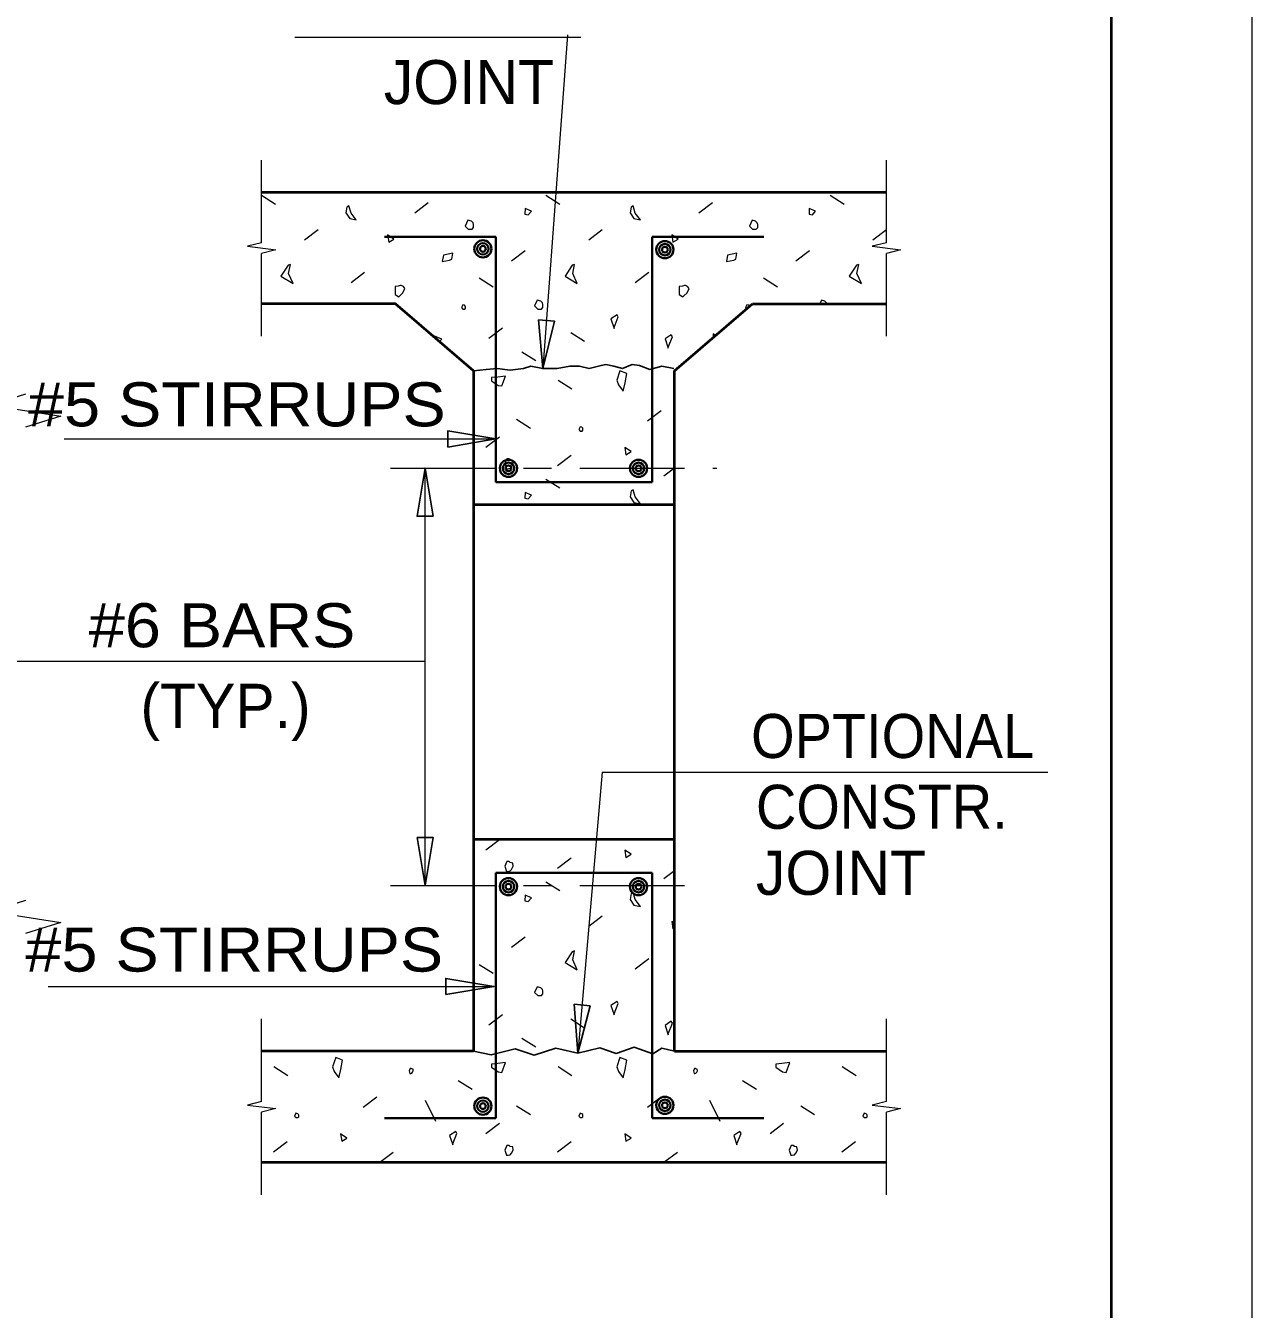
# Model space of a CAD drawing. Extents: x 0 to 34, y 0 to 23.4.
# Drawn here: x 29.648 to 34, y 4.606 to 9.162 of the extents above; entities that cross this region are included whole.
import ezdxf
from ezdxf.enums import TextEntityAlignment as Align

# ---------------------------------------------------------------- set-up
doc = ezdxf.new("R2010")
doc.units = 0
doc.header["$LTSCALE"] = 0.062
doc.linetypes.add('LONG_DASH_SHORT_DASH', pattern=[9.9, 6, -1.2, 1.5, -1.2])
doc.linetypes.add('SHORT_DASHED', pattern=[2.7, 1.5, -1.2])
for name, color, linetype, lineweight in [('1', 7, 'Continuous', 40), ('2', 7, 'SHORT_DASHED', 13), ('3', 7, 'Continuous', 35), ('4', 7, 'Continuous', 13), ('7', 7, 'Continuous', 13)]:
    doc.layers.add(name, color=color, linetype=linetype, lineweight=lineweight)

msp = doc.modelspace()

# ---------------------------------------------------------------- linework, layer by layer
at = {"layer": '1', "lineweight": 13}
for p, q in [((30.485, 8.39125), (30.485, 8.685)), ((32.70167, 8.39125), (32.70167, 8.685)), ((30.485, 8.06), (30.485, 8.35375)), ((32.70167, 8.06), (32.70167, 8.35375)), ((30.485, 5.34333), (30.485, 5.63708)), ((32.70167, 5.34333), (32.70167, 5.63708)), ((30.485, 5.01208), (30.485, 5.30583)), ((32.70167, 5.01208), (32.70167, 5.30583))]:
    msp.add_line(p, q, dxfattribs=at)
at = {"layer": '1'}
for p, q in [((30.485, 8.57042), (32.70167, 8.57042)), ((31.94958, 7.93708), (32.22667, 8.17458)), ((32.22667, 8.17458), (32.70167, 8.17458)), ((31.23708, 7.93708), (31.23708, 5.5225)), ((31.94958, 5.5225), (31.94958, 7.93708)), ((31.23708, 7.46208), (31.94958, 7.46208)), ((31.23708, 6.27458), (31.94958, 6.27458)), ((31.23708, 5.5225), (30.485, 5.5225)), ((31.94958, 5.5225), (32.70167, 5.5225)), ((32.70167, 5.12667), (30.485, 5.12667))]:
    msp.add_line(p, q, dxfattribs=at)
at = {"layer": '1', "lineweight": 13}
for points in [[(34, 0), (34, 22), (0, 22)], [(30.485, 8.39125), (30.435, 8.37875), (30.535, 8.36625), (30.485, 8.35375)], [(32.70167, 8.39125), (32.65167, 8.37875), (32.75167, 8.36625), (32.70167, 8.35375)], [(29.6476, 7.85406), (29.5226, 7.815), (29.7726, 7.77594), (29.6476, 7.73688)], [(29.6476, 6.05719), (29.5226, 6.01813), (29.7726, 5.97906), (29.6476, 5.94)], [(30.485, 5.34333), (30.435, 5.33083), (30.535, 5.31833), (30.485, 5.30583)], [(32.70167, 5.34333), (32.65167, 5.33083), (32.75167, 5.31833), (32.70167, 5.30583)]]:
    msp.add_lwpolyline(points, dxfattribs=at)
at = {"layer": '1'}
msp.add_lwpolyline([(33.5, 0.5), (33.5, 21.5), (1.5, 21.5), (1.5, 0.5)], close=True, dxfattribs=at)
msp.add_lwpolyline([(31.23708, 7.93708), (30.96, 8.17458), (30.485, 8.17458)], dxfattribs=at)
at = {"layer": '1', "lineweight": 25}
for points in [[(31.23708, 7.93708), (31.2813, 7.94203), (31.32099, 7.94484), (31.36625, 7.93922), (31.41443, 7.94484), (31.43995, 7.95333), (31.48245, 7.94484), (31.53339, 7.94484), (31.5787, 7.95333), (31.61271, 7.95333), (31.64672, 7.94484), (31.68917, 7.9562), (31.7062, 7.95906), (31.73448, 7.95333), (31.76568, 7.94484), (31.79964, 7.95906), (31.8251, 7.9562), (31.86193, 7.94203), (31.90443, 7.95333), (31.94693, 7.94484)], [(31.23708, 5.5225), (31.2999, 5.50932), (31.38474, 5.5312), (31.45156, 5.50802), (31.5287, 5.5325), (31.60708, 5.51578), (31.68547, 5.53375), (31.74333, 5.51448), (31.8063, 5.53635), (31.87313, 5.51318), (31.90526, 5.5325), (31.94958, 5.5225)]]:
    msp.add_lwpolyline(points, dxfattribs=at)
at = {"layer": '2', "linetype": 'LONG_DASH_SHORT_DASH'}
for p, q in [((30.94188, 7.59188), (32.10052, 7.59188)), ((30.94188, 6.11021), (32.01578, 6.11021))]:
    msp.add_line(p, q, dxfattribs=at)
at = {"layer": '3'}
for p, q in [((30.92042, 8.41208), (31.31625, 8.41208)), ((31.31625, 8.41208), (31.31625, 7.54125)), ((31.87042, 8.41208), (31.87042, 7.54125)), ((31.87042, 8.41208), (32.26625, 8.41208)), ((31.31625, 7.54125), (31.87042, 7.54125)), ((31.31625, 5.285), (31.31625, 6.15583)), ((31.31625, 6.15583), (31.87042, 6.15583)), ((31.87042, 5.285), (31.87042, 6.15583)), ((30.92042, 5.285), (31.31625, 5.285)), ((31.87042, 5.285), (32.26625, 5.285))]:
    msp.add_line(p, q, dxfattribs=at)
for centre, radius in [((31.26998, 8.36974), 0.03048), ((31.26998, 8.36974), 0.02032), ((31.91579, 8.36692), 0.03048), ((31.91579, 8.36692), 0.02032), ((31.26998, 8.36974), 0.01016), ((31.91579, 8.36692), 0.01016), ((31.36063, 7.59084), 0.03048), ((31.36063, 7.59084), 0.02032), ((31.82232, 7.59084), 0.03048), ((31.82232, 7.59084), 0.02032), ((31.36063, 7.59084), 0.01016), ((31.82232, 7.59084), 0.01016), ((31.36063, 6.10623), 0.03048), ((31.36063, 6.10623), 0.02032), ((31.36063, 6.10623), 0.01016), ((31.82232, 6.10623), 0.03048), ((31.82232, 6.10623), 0.02032), ((31.82232, 6.10623), 0.01016), ((31.26998, 5.32733), 0.03048), ((31.26998, 5.32733), 0.02032), ((31.26998, 5.32733), 0.01016), ((31.91579, 5.33015), 0.03048), ((31.91579, 5.33015), 0.02032), ((31.91579, 5.33015), 0.01016)]:
    msp.add_circle(centre, radius, dxfattribs=at)
at = {"layer": '4'}
for p, q in [((30.6025, 9.12057), (31.61797, 9.12057)), ((31.57026, 9.12922), (31.48245, 7.94484)), ((29.78427, 7.695), (31.31625, 7.695)), ((31.06495, 6.11021), (31.06495, 7.59188)), ((29.3401, 6.90651), (31.06495, 6.90651)), ((31.69302, 6.51234), (31.60708, 5.51578)), ((31.69302, 6.51234), (33.27432, 6.51234)), ((29.72797, 5.75203), (31.30927, 5.75203))]:
    msp.add_line(p, q, dxfattribs=at)
at = {"layer": '4', "lineweight": 25}
for points in [[(31.46667, 8.1175), (31.52354, 8.11328), (31.48245, 7.94484)], [(31.14526, 7.66651), (31.14526, 7.72349), (31.31625, 7.695)], [(31.09344, 7.42089), (31.03646, 7.42089), (31.06495, 7.59188)], [(31.03646, 6.2812), (31.09344, 6.2812), (31.06495, 6.11021)], [(31.13828, 5.72354), (31.13828, 5.78052), (31.30927, 5.75203)], [(31.59339, 5.68859), (31.65016, 5.6837), (31.60708, 5.51578)]]:
    msp.add_lwpolyline(points, close=True, dxfattribs=at)
at = {"layer": '7'}
for p, q in [((30.485, 8.56), (30.53448, 8.52875)), ((31.07635, 8.53307), (31.02823, 8.49646)), ((31.49339, 8.56), (31.54286, 8.52875)), ((32.08474, 8.53307), (32.03661, 8.49646)), ((32.50177, 8.56), (32.55125, 8.52875)), ((30.68526, 8.4375), (30.63714, 8.40089)), ((31.69365, 8.4375), (31.64552, 8.40089)), ((32.70167, 8.43724), (32.65391, 8.40089)), ((31.4201, 8.36281), (31.37198, 8.3262)), ((32.42849, 8.36281), (32.38036, 8.3262)), ((30.85031, 8.28635), (30.80219, 8.24974)), ((31.25708, 8.26672), (31.30661, 8.23552)), ((31.8587, 8.28635), (31.81057, 8.24974)), ((32.26547, 8.26672), (32.315, 8.23552)), ((32.47115, 8.18729), (32.46531, 8.17458)), ((31.33901, 8.08807), (31.29089, 8.05146)), ((31.58146, 8.07313), (31.63089, 8.04208)), ((32.08745, 8.06776), (32.08687, 8.05474)), ((32.09734, 8.06375), (32.08745, 8.06776)), ((31.40792, 8.00484), (31.45745, 7.97359)), ((31.53651, 7.90411), (31.58594, 7.87281)), ((31.90214, 7.79536), (31.85401, 7.75875)), ((31.38917, 7.76474), (31.43865, 7.73349)), ((31.3287, 7.70161), (31.28057, 7.665)), ((31.58333, 7.63661), (31.53521, 7.6)), ((31.94958, 7.59141), (31.91234, 7.56307)), ((31.49339, 7.55266), (31.54286, 7.52141)), ((31.3287, 6.27255), (31.28057, 6.23594)), ((31.58333, 6.20755), (31.53521, 6.17094)), ((31.94958, 6.16234), (31.91234, 6.13401)), ((31.49339, 6.12359), (31.54286, 6.09234)), ((31.69365, 6.00109), (31.64552, 5.96448)), ((31.94958, 5.97656), (31.94031, 5.98271)), ((31.4201, 5.92641), (31.37198, 5.88979)), ((31.8587, 5.84995), (31.81057, 5.81333)), ((31.25708, 5.83031), (31.30661, 5.79911)), ((31.33901, 5.65167), (31.29089, 5.61505)), ((31.58146, 5.63672), (31.63089, 5.60568)), ((31.40792, 5.56844), (31.45745, 5.53719)), ((30.52813, 5.46771), (30.57755, 5.43641)), ((31.53651, 5.46771), (31.58594, 5.43641)), ((32.5449, 5.46771), (32.59432, 5.43641)), ((31.18281, 5.41865), (31.23229, 5.3874)), ((32.1912, 5.41865), (32.24068, 5.3874)), ((30.89375, 5.35896), (30.84563, 5.32234)), ((31.06531, 5.34786), (31.10198, 5.27432)), ((31.90214, 5.35896), (31.85401, 5.32234)), ((32.0737, 5.34786), (32.11036, 5.27432)), ((31.38917, 5.32833), (31.43865, 5.29708)), ((32.39755, 5.32833), (32.44703, 5.29708)), ((31.3287, 5.26521), (31.28057, 5.22859)), ((32.33708, 5.26521), (32.28896, 5.22859)), ((30.57495, 5.20021), (30.52682, 5.16359)), ((31.58333, 5.20021), (31.53521, 5.16359)), ((32.59172, 5.20021), (32.54359, 5.16359)), ((30.95208, 5.16328), (30.90396, 5.12667)), ((31.96047, 5.16328), (31.91234, 5.12667))]:
    msp.add_line(p, q, dxfattribs=at)
for points in [[(30.78776, 8.51813), (30.7837, 8.4974), (30.79745, 8.47708), (30.82047, 8.47255), (30.80208, 8.49693), (30.79422, 8.52224)], [(31.79615, 8.51813), (31.79208, 8.4974), (31.80583, 8.47708), (31.82885, 8.47255), (31.81047, 8.49693), (31.8026, 8.52224)], [(31.41969, 8.51266), (31.4188, 8.49286), (31.43073, 8.4901), (31.44224, 8.50344)], [(32.42807, 8.51266), (32.42719, 8.49286), (32.43911, 8.4901), (32.45063, 8.50344)], [(31.21672, 8.47104), (31.20745, 8.45083), (31.21828, 8.43958), (31.23151, 8.43958), (31.23693, 8.44547), (31.23693, 8.45625), (31.2351, 8.46156), (31.22938, 8.4675)], [(32.2251, 8.47104), (32.21583, 8.45083), (32.22667, 8.43958), (32.2399, 8.43958), (32.24531, 8.44547), (32.24531, 8.45625), (32.24349, 8.46156), (32.23776, 8.4675)], [(30.93193, 8.41911), (30.93563, 8.39328), (30.95411, 8.40437)], [(31.94031, 8.41911), (31.94401, 8.39328), (31.9625, 8.40437)], [(31.12974, 8.34745), (31.12604, 8.32542), (31.15188, 8.32911), (31.15917, 8.33271), (31.16286, 8.35484)], [(32.13813, 8.34745), (32.13443, 8.32542), (32.16026, 8.32911), (32.16755, 8.33271), (32.17125, 8.35484)], [(30.57865, 8.31177), (30.55292, 8.27323), (30.5962, 8.24729), (30.58042, 8.28234), (30.58708, 8.31443)], [(31.58703, 8.31177), (31.5613, 8.27323), (31.60458, 8.24729), (31.5888, 8.28234), (31.59547, 8.31443)], [(32.59542, 8.31177), (32.56969, 8.27323), (32.61297, 8.24729), (32.59719, 8.28234), (32.60385, 8.31443)], [(30.95849, 8.23604), (30.95849, 8.20813), (30.97115, 8.19917), (30.975, 8.20276), (30.98583, 8.21385), (30.99323, 8.22865), (30.98786, 8.23604), (30.98047, 8.23958), (30.97688, 8.23958), (30.96964, 8.23755)], [(31.96688, 8.23604), (31.96688, 8.20813), (31.97953, 8.19917), (31.98339, 8.20276), (31.99422, 8.21385), (32.00161, 8.22865), (31.99625, 8.23604), (31.98885, 8.23958), (31.98526, 8.23958), (31.97802, 8.23755)], [(31.19828, 8.17167), (31.19365, 8.16156), (31.19906, 8.15594), (31.20568, 8.15594), (31.20839, 8.15885), (31.20839, 8.16427), (31.2075, 8.16693), (31.20464, 8.1699)], [(31.46276, 8.18729), (31.45349, 8.16708), (31.46432, 8.15583), (31.47755, 8.15583), (31.48297, 8.16172), (31.48297, 8.1725), (31.48115, 8.17781), (31.47542, 8.18375)], [(31.72396, 8.12089), (31.73531, 8.08766), (31.73531, 8.0912), (31.7501, 8.12823), (31.74635, 8.13557)], [(31.91615, 8.05016), (31.92755, 8.01698), (31.92755, 8.02052), (31.94224, 8.05755), (31.93849, 8.0649)], [(31.7563, 7.93651), (31.7451, 7.90339), (31.75078, 7.88682), (31.76734, 7.86469), (31.77469, 7.89417), (31.78021, 7.92734)], [(31.32255, 7.91458), (31.30047, 7.91271), (31.30047, 7.90167), (31.32443, 7.88516), (31.3374, 7.88328), (31.35031, 7.91823)], [(31.61479, 7.73865), (31.61016, 7.72849), (31.61557, 7.72286), (31.62219, 7.72286), (31.6249, 7.72583), (31.6249, 7.73125), (31.62401, 7.73391), (31.62115, 7.73688)], [(31.7737, 7.6649), (31.7774, 7.63906), (31.79589, 7.65016)], [(31.34797, 7.60776), (31.3538, 7.58932), (31.35911, 7.58932), (31.36661, 7.59115), (31.37203, 7.59651), (31.3774, 7.60776), (31.37589, 7.6187), (31.36661, 7.62063), (31.36271, 7.62443), (31.35536, 7.62443)], [(31.41969, 7.50531), (31.4188, 7.48552), (31.43073, 7.48276), (31.44224, 7.49609)], [(31.79615, 7.51078), (31.79208, 7.49005), (31.80583, 7.46974), (31.82885, 7.46521), (31.81047, 7.48958), (31.8026, 7.5149)], [(31.7737, 6.23583), (31.7774, 6.21), (31.79589, 6.22109)], [(31.34797, 6.1787), (31.3538, 6.16026), (31.35911, 6.16026), (31.36661, 6.16208), (31.37203, 6.16745), (31.3774, 6.1787), (31.37589, 6.18964), (31.36661, 6.19156), (31.36271, 6.19536), (31.35536, 6.19536)], [(31.41969, 6.07625), (31.4188, 6.05646), (31.43073, 6.0537), (31.44224, 6.06703)], [(31.79615, 6.08172), (31.79208, 6.06099), (31.80583, 6.04068), (31.82885, 6.03615), (31.81047, 6.06052), (31.8026, 6.08583)], [(31.58703, 5.87536), (31.5613, 5.83682), (31.60458, 5.81089), (31.5888, 5.84594), (31.59547, 5.87802)], [(31.46276, 5.75089), (31.45349, 5.73068), (31.46432, 5.71943), (31.47755, 5.71943), (31.48297, 5.72531), (31.48297, 5.73609), (31.48115, 5.74141), (31.47542, 5.74734)], [(31.72396, 5.68448), (31.73531, 5.65125), (31.73531, 5.65479), (31.7501, 5.69182), (31.74635, 5.69917)], [(31.91615, 5.61375), (31.92755, 5.58057), (31.92755, 5.58411), (31.94224, 5.62115), (31.93849, 5.62849)], [(30.74792, 5.5001), (30.73672, 5.46698), (30.7424, 5.45042), (30.75896, 5.42828), (30.7663, 5.45776), (30.77182, 5.49094)], [(31.32255, 5.47818), (31.30047, 5.4763), (31.30047, 5.46526), (31.32443, 5.44875), (31.3374, 5.44688), (31.35031, 5.48182)], [(31.7563, 5.5001), (31.7451, 5.46698), (31.75078, 5.45042), (31.76734, 5.42828), (31.77469, 5.45776), (31.78021, 5.49094)], [(32.33094, 5.47818), (32.30885, 5.4763), (32.30885, 5.46526), (32.33281, 5.44875), (32.34578, 5.44688), (32.3587, 5.48182)], [(31.00833, 5.45286), (31.01125, 5.44365), (31.01391, 5.44365), (31.01766, 5.44458), (31.02036, 5.44724), (31.02302, 5.45286), (31.02229, 5.45839), (31.01766, 5.45932), (31.01568, 5.46125), (31.01203, 5.46125)], [(32.01672, 5.45286), (32.01964, 5.44365), (32.02229, 5.44365), (32.02604, 5.44458), (32.02875, 5.44724), (32.03141, 5.45286), (32.03068, 5.45839), (32.02604, 5.45932), (32.02406, 5.46125), (32.02042, 5.46125)], [(30.60641, 5.30224), (30.60177, 5.29208), (30.60719, 5.28646), (30.6138, 5.28646), (30.61651, 5.28943), (30.61651, 5.29484), (30.61563, 5.2975), (30.61276, 5.30047)], [(31.61479, 5.30224), (31.61016, 5.29208), (31.61557, 5.28646), (31.62219, 5.28646), (31.6249, 5.28943), (31.6249, 5.29484), (31.62401, 5.2975), (31.62115, 5.30047)], [(32.62318, 5.30224), (32.61854, 5.29208), (32.62396, 5.28646), (32.63057, 5.28646), (32.63328, 5.28943), (32.63328, 5.29484), (32.6324, 5.2975), (32.62953, 5.30047)], [(30.76531, 5.22849), (30.76901, 5.20266), (30.7875, 5.21375)], [(31.15135, 5.22307), (31.16276, 5.18984), (31.16276, 5.19344), (31.17745, 5.23042), (31.1737, 5.23776)], [(31.7737, 5.22849), (31.7774, 5.20266), (31.79589, 5.21375)], [(32.15974, 5.22307), (32.17115, 5.18984), (32.17115, 5.19344), (32.18583, 5.23042), (32.18208, 5.23776)], [(31.34797, 5.17135), (31.3538, 5.15292), (31.35911, 5.15292), (31.36661, 5.15474), (31.37203, 5.1601), (31.3774, 5.17135), (31.37589, 5.18229), (31.36661, 5.18422), (31.36271, 5.18802), (31.35536, 5.18802)], [(32.35635, 5.17135), (32.36219, 5.15292), (32.3675, 5.15292), (32.375, 5.15474), (32.38042, 5.1601), (32.38578, 5.17135), (32.38427, 5.18229), (32.375, 5.18422), (32.37109, 5.18802), (32.36375, 5.18802)]]:
    msp.add_lwpolyline(points, close=True, dxfattribs=at)
for points in [[(32.20667, 8.17167), (32.20203, 8.16156), (32.2063, 8.15714)], [(32.2163, 8.16568), (32.21589, 8.16693), (32.21302, 8.1699), (32.20667, 8.17167)], [(32.49063, 8.17458), (32.48953, 8.17781), (32.4838, 8.18375), (32.47115, 8.18729)], [(31.11656, 8.04042), (31.12422, 8.04932), (31.08969, 8.06344)], [(31.94031, 5.98271), (31.94401, 5.95688), (31.94958, 5.96021)]]:
    msp.add_lwpolyline(points, dxfattribs=at)

# ---------------------------------------------------------------- texts
at = {"layer": '4'}
msp.add_text('JOINT', height=0.1563, dxfattribs=at).set_placement((31.52219, 8.88339), align=Align.RIGHT)
at = {"layer": '4', "width": 1.1}
for p in [(31.13807, 7.73979), (31.12885, 5.80474)]:
    msp.add_text('#5 STIRRUPS', height=0.1563, dxfattribs=at).set_placement(p, align=Align.RIGHT)
msp.add_text('#6 BARS', height=0.1563, dxfattribs=at).set_placement((30.34453, 6.95583), align=Align.CENTER)
at = {"layer": '4'}
msp.add_text('(TYP.)', height=0.1563, dxfattribs=at).set_placement((30.35688, 6.66984), align=Align.CENTER)
at = {"layer": '4', "width": 0.95}
for s, p in [('OPTIONAL', (32.22151, 6.56276)), ('CONSTR.', (32.23875, 6.31141))]:
    msp.add_text(s, height=0.1563, dxfattribs=at).set_placement(p)
at = {"layer": '4'}
msp.add_text('JOINT', height=0.1563, dxfattribs=at).set_placement((32.23875, 6.07703))

doc.saveas('drawing.dxf')
